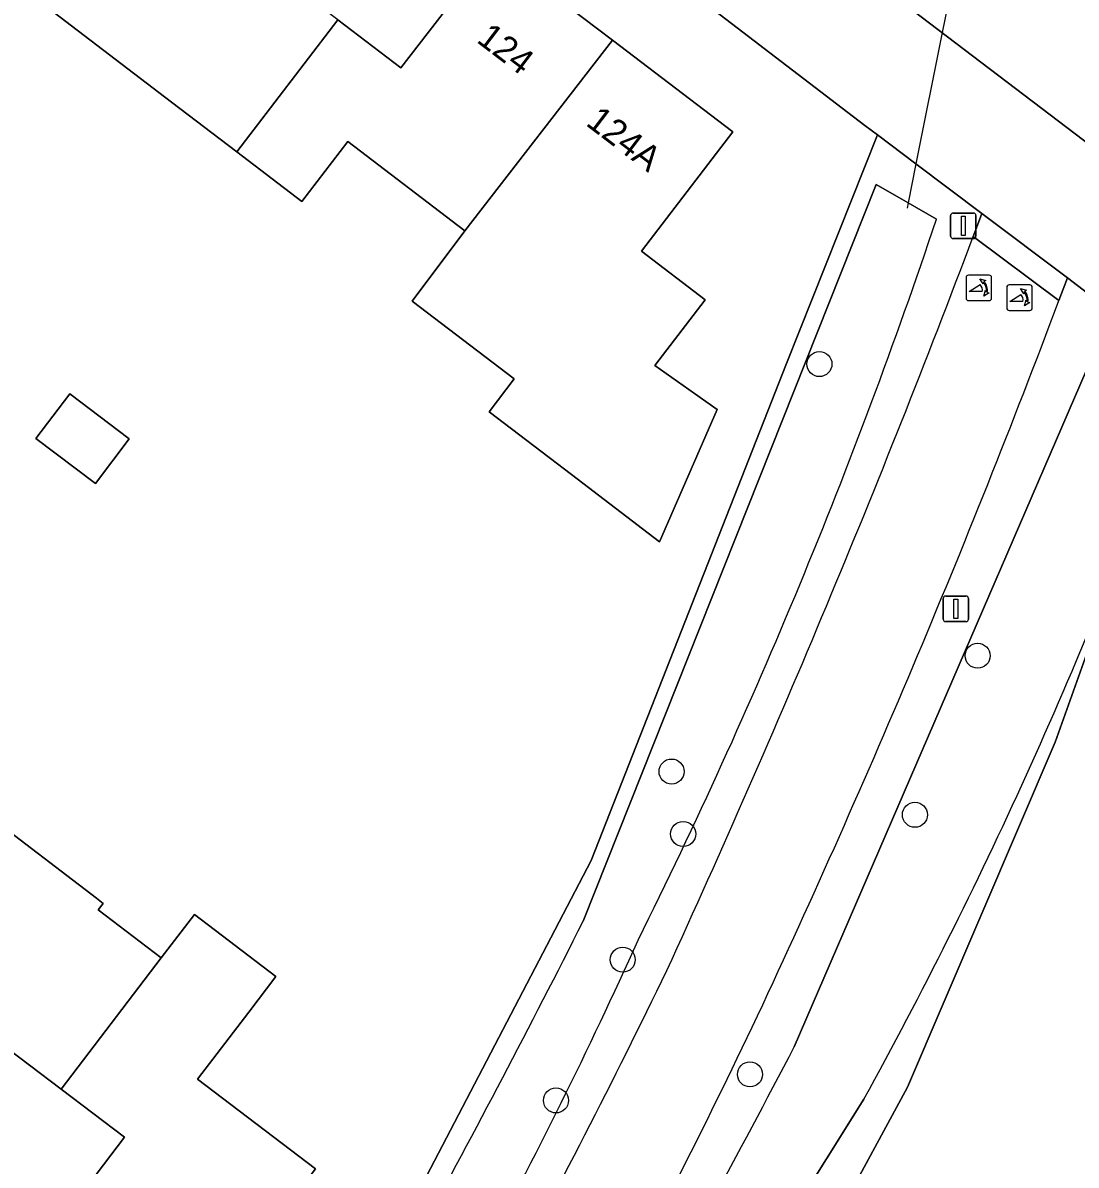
# Model space of a CAD drawing. Extents: x 159626 to 160723, y 388173 to 389416.
# Drawn here: x 160399.5 to 160440.65, y 388606.29 to 388650.92 of the extents above; entities that cross this region are included whole.
import ezdxf

# ---------------------------------------------------------------- set-up
doc = ezdxf.new("R2010")
doc.units = 0
for name, color, linetype in [('IMGEO_Berm_groen', 7, 'Continuous'), ('IMGEO_Boom', 7, 'Continuous'), ('IMGEO_Duiker', 7, 'Continuous'), ('IMGEO_Erf', 7, 'Continuous'), ('IMGEO_Fietspad_gesloten', 7, 'Continuous'), ('IMGEO_Lichtmast', 7, 'Continuous'), ('IMGEO_Pand', 7, 'Continuous'), ('IMGEO_Pand_nummerreeks', 7, 'Continuous'), ('IMGEO_Poller', 7, 'Continuous'), ('IMGEO_Rijbaan_lokaal_open', 7, 'Continuous'), ('IMGEO_Verkeersbordpaal', 7, 'Continuous'), ('IMGEO_Voetpad_open', 7, 'Continuous'), ('IMGEO_Waterloop', 7, 'Continuous')]:
    doc.layers.add(name, color=color, linetype=linetype)

msp = doc.modelspace()

# ---------------------------------------------------------------- linework, layer by layer
at = {"layer": 'IMGEO_Berm_groen'}
for points in [[(160436.965, 388643.472), (160434.385, 388645.415), (160432.882, 388646.546), (160429.331, 388637.607), (160421.697, 388618.19), (160411.017, 388597.713), (160407.654, 388591.157), (160410.924, 388588.72)], [(160421.39, 388615.827), (160432.829, 388644.603), (160434.08, 388643.886), (160435.187, 388643.251)], [(160436.628, 388642.576), (160436.797, 388643.024), (160436.965, 388643.472)], [(160429.634, 388610.908), (160441.529, 388638.466), (160442.538, 388637.837), (160444.706, 388636.484), (160445.015, 388637.348), (160442.866, 388638.996), (160440.306, 388640.958), (160440.14, 388640.514), (160439.973, 388640.071)], [(160426.76, 388595.873), (160434.06, 388609.33), (160439.82, 388622.82), (160444.055, 388634.663)], [(160432.356, 388608.864), (160417.502, 388585.138), (160416.544, 388585.792), (160415.731, 388586.347)]]:
    msp.add_lwpolyline(points, dxfattribs=at)
for centre, radius, start, end in [((160226.048, 388713.301), 220.559, 333.55502, 341.48192), ((160017.272, 388800.831), 448.223, 335.35161, 339.3247), ((160074.328, 388777.667), 390.678, 334.85848, 339.37824), ((160271.208, 388697.491), 183.911, 331.19029, 340.02424), ((160041.141, 388807.495), 425.823, 329.54554, 333.24916), ((160256.085, 388690.215), 183.529, 327.06662, 335.83276), ((160162.588, 388740.475), 291.034, 328.57145, 334.22007), ((160187.153, 388726.776), 266.927, 328.24692, 334.45817), ((160048.912, 388810.204), 429.73, 328.60572, 332.36935)]:
    msp.add_arc(centre, radius, start, end, dxfattribs=at)
at = {"layer": 'IMGEO_Boom'}
for centre in [(160430.617, 388637.59), (160436.797, 388626.194), (160424.838, 388621.669), (160434.346, 388619.978), (160425.293, 388619.229), (160422.931, 388614.317), (160427.902, 388609.836), (160420.323, 388608.816)]:
    msp.add_circle(centre, 0.489, dxfattribs=at)
at = {"layer": 'IMGEO_Duiker'}
msp.add_lwpolyline([(160439.097, 388669.047), (160438.998, 388668.552), (160437.72, 388662.006), (160437.338, 388659.826), (160436.892, 388657.762), (160435.422, 388650.617), (160434.385, 388645.415), (160434.08, 388643.886), (160434.039, 388643.681)], dxfattribs=at)
at = {"layer": 'IMGEO_Erf'}
for points in [[(160356.325, 388630.244), (160407.654, 388591.157), (160411.017, 388597.713), (160421.697, 388618.19), (160429.331, 388637.607), (160432.882, 388646.546), (160432.389, 388646.917), (160387.612, 388681.185)], [(160411.806, 388651.036), (160414.264, 388649.166), (160417.85, 388653.808), (160422.533, 388650.244), (160427.228, 388646.671), (160423.669, 388641.996), (160426.146, 388640.101), (160424.19, 388637.54), (160426.626, 388635.819), (160424.37, 388630.648), (160420.93, 388633.27), (160417.712, 388635.723), (160418.693, 388637.01), (160414.71, 388640.047), (160416.757, 388642.798), (160412.188, 388646.282), (160410.401, 388643.937), (160407.85, 388645.882), (160405.307, 388647.822), (160400.68, 388651.352)], [(160473.922, 388615.363), (160452.411, 388631.678), (160445.015, 388637.348), (160444.706, 388636.484), (160444.055, 388634.663), (160439.82, 388622.82), (160434.06, 388609.33), (160426.76, 388595.873), (160418.317, 388583.095), (160421.291, 388580.817), (160422.334, 388579.975)], [(160397.998, 388620.049), (160402.373, 388616.718), (160402.636, 388616.517), (160402.442, 388616.263), (160404.906, 388614.386), (160406.197, 388616.078), (160409.378, 388613.655), (160408.321, 388612.267), (160406.325, 388609.648), (160410.93, 388606.14), (160405.212, 388598.62), (160399.901, 388602.678), (160403.463, 388607.383), (160400.99, 388609.256), (160398.507, 388611.135)]]:
    msp.add_lwpolyline(points, dxfattribs=at)
msp.add_lwpolyline([(160403.654, 388634.669), (160402.335, 388632.923), (160400.008, 388634.681), (160401.328, 388636.427)], close=True, dxfattribs=at)
at = {"layer": 'IMGEO_Fietspad_gesloten'}
msp.add_lwpolyline([(160439.973, 388640.071), (160436.628, 388642.576)], dxfattribs=at)
for centre, radius, start, end in [((160017.272, 388800.831), 448.223, 335.35161, 339.3247), ((160074.328, 388777.667), 390.678, 334.85848, 339.37824), ((160162.588, 388740.475), 291.034, 328.57145, 334.22007), ((160187.153, 388726.776), 266.927, 328.24692, 334.45817)]:
    msp.add_arc(centre, radius, start, end, dxfattribs=at)
at = {"layer": 'IMGEO_Lichtmast'}
for p, q in [((160435.449, 388627.627), (160435.449, 388628.427)), ((160435.449, 388628.427), (160435.449, 388627.627)), ((160435.549, 388628.527), (160436.339, 388628.527)), ((160436.339, 388628.527), (160435.549, 388628.527)), ((160436.439, 388628.427), (160436.439, 388627.627)), ((160436.439, 388627.627), (160436.439, 388628.427)), ((160436.339, 388627.527), (160435.549, 388627.527)), ((160435.549, 388627.527), (160436.339, 388627.527))]:
    msp.add_line(p, q, dxfattribs=at)
msp.add_lwpolyline([(160435.869, 388628.402), (160436.019, 388628.402), (160436.019, 388627.652), (160435.869, 388627.652), (160435.869, 388628.402)], dxfattribs=at)
for centre, start, end in [((160435.549, 388628.427), 90, 180), ((160435.549, 388628.427), 90, 180), ((160436.339, 388628.427), 0, 90), ((160436.339, 388628.427), 360, 90), ((160435.549, 388627.627), 180, 270), ((160435.549, 388627.627), 180, 270), ((160436.339, 388627.627), 270, 0), ((160436.339, 388627.627), 270, 0)]:
    msp.add_arc(centre, 0.1, start, end, dxfattribs=at)
at = {"layer": 'IMGEO_Pand'}
for points in [[(160407.85, 388645.882), (160411.806, 388651.036), (160409.34, 388652.912), (160412.874, 388657.59), (160408.217, 388661.161), (160400.68, 388651.352), (160405.307, 388647.822)], [(160416.757, 388642.798), (160422.533, 388650.244), (160417.85, 388653.808), (160414.264, 388649.166), (160411.806, 388651.036), (160407.85, 388645.882), (160410.401, 388643.937), (160412.188, 388646.282)], [(160423.669, 388641.996), (160427.228, 388646.671), (160422.533, 388650.244), (160416.757, 388642.798), (160414.71, 388640.047), (160418.693, 388637.01), (160417.712, 388635.723), (160420.93, 388633.27), (160424.37, 388630.648), (160426.626, 388635.819), (160424.19, 388637.54), (160426.146, 388640.101)], [(160403.654, 388634.669), (160401.328, 388636.427), (160400.008, 388634.681), (160402.335, 388632.923)], [(160404.906, 388614.386), (160402.442, 388616.263), (160402.636, 388616.517), (160402.373, 388616.718), (160397.998, 388620.049), (160390.272, 388610.022), (160394.951, 388606.438), (160398.507, 388611.135), (160400.99, 388609.256)], [(160404.906, 388614.386), (160400.99, 388609.256), (160403.463, 388607.383), (160399.901, 388602.678), (160405.212, 388598.62), (160410.93, 388606.14), (160406.325, 388609.648), (160408.321, 388612.267), (160409.378, 388613.655), (160406.197, 388616.078)]]:
    msp.add_lwpolyline(points, close=True, dxfattribs=at)
at = {"layer": 'IMGEO_Poller'}
for p, q in [((160436.343, 388640.97), (160436.343, 388640.163)), ((160436.343, 388640.97), (160436.343, 388640.163)), ((160437.245, 388641.065), (160436.437, 388641.065)), ((160437.245, 388641.065), (160436.437, 388641.065)), ((160437.339, 388640.163), (160437.339, 388640.97)), ((160437.339, 388640.163), (160437.339, 388640.97)), ((160438.835, 388640.683), (160438.027, 388640.683)), ((160438.835, 388640.683), (160438.027, 388640.683)), ((160437.933, 388640.588), (160437.933, 388639.781)), ((160437.933, 388640.588), (160437.933, 388639.781)), ((160438.929, 388639.781), (160438.929, 388640.588)), ((160438.929, 388639.781), (160438.929, 388640.588)), ((160436.437, 388640.068), (160437.245, 388640.068)), ((160436.437, 388640.068), (160437.245, 388640.068)), ((160438.027, 388639.686), (160438.835, 388639.686)), ((160438.027, 388639.686), (160438.835, 388639.686))]:
    msp.add_line(p, q, dxfattribs=at)
for points in [[(160436.978, 388640.421), (160436.465, 388640.421), (160436.895, 388640.696)], [(160437.022, 388640.794), (160437.01, 388640.721), (160436.885, 388640.926)], [(160436.885, 388640.926), (160437.116, 388640.86), (160437.045, 388640.828)], [(160437.038, 388640.249), (160437.104, 388640.48), (160437.134, 388640.412)], [(160437.17, 388640.385), (160437.242, 388640.374), (160437.038, 388640.249)], [(160438.568, 388640.039), (160438.055, 388640.039), (160438.485, 388640.314)], [(160438.612, 388640.412), (160438.6, 388640.339), (160438.475, 388640.544)], [(160438.475, 388640.544), (160438.706, 388640.478), (160438.635, 388640.446)], [(160438.628, 388639.867), (160438.694, 388640.098), (160438.724, 388640.03)], [(160438.76, 388640.003), (160438.832, 388639.992), (160438.628, 388639.867)]]:
    msp.add_lwpolyline(points, dxfattribs=at)
for centre, radius, start, end in [((160436.437, 388640.97), 0.0946, 90, 180), ((160436.437, 388640.97), 0.0946, 90, 180), ((160436.65, 388640.471), 0.332, 351.3247, 42.4854), ((160436.664, 388640.481), 0.476, 351.7527, 41.1691), ((160436.664, 388640.481), 0.516, 349.3569, 42.2912), ((160437.245, 388640.97), 0.0946, 0, 90), ((160437.245, 388640.97), 0.0946, 0, 90), ((160438.027, 388640.588), 0.0946, 90, 180), ((160438.027, 388640.588), 0.0946, 90, 180), ((160438.835, 388640.588), 0.0946, 0, 90), ((160438.835, 388640.588), 0.0946, 0, 90), ((160438.24, 388640.089), 0.332, 351.3247, 42.4854), ((160438.254, 388640.099), 0.476, 351.7527, 41.1691), ((160438.254, 388640.099), 0.516, 349.3569, 42.2912), ((160436.437, 388640.163), 0.0946, 180, 270), ((160436.437, 388640.163), 0.0946, 180, 270), ((160437.245, 388640.163), 0.0946, 270, 0), ((160437.245, 388640.163), 0.0946, 270, 0), ((160438.027, 388639.781), 0.0946, 180, 270), ((160438.027, 388639.781), 0.0946, 180, 270), ((160438.835, 388639.781), 0.0946, 270, 0), ((160438.835, 388639.781), 0.0946, 270, 0)]:
    msp.add_arc(centre, radius, start, end, dxfattribs=at)
at = {"layer": 'IMGEO_Rijbaan_lokaal_open'}
msp.add_lwpolyline([(160435.247, 388658.875), (160434.926, 388659.154), (160430.911, 388653.976), (160445.327, 388643.009), (160449.379, 388648.196), (160446.896, 388650.101)], dxfattribs=at)
msp.add_lwpolyline([(160436.628, 388642.576), (160439.973, 388640.071), (160440.14, 388640.514), (160440.306, 388640.958), (160436.965, 388643.472), (160436.797, 388643.024)], close=True, dxfattribs=at)
at = {"layer": 'IMGEO_Verkeersbordpaal'}
for p, q in [((160435.74, 388642.593), (160435.74, 388643.393)), ((160435.74, 388643.393), (160435.74, 388642.593)), ((160435.84, 388643.493), (160436.63, 388643.493)), ((160436.63, 388643.493), (160435.84, 388643.493)), ((160436.73, 388643.393), (160436.73, 388642.593)), ((160436.73, 388642.593), (160436.73, 388643.393)), ((160436.63, 388642.493), (160435.84, 388642.493)), ((160435.84, 388642.493), (160436.63, 388642.493))]:
    msp.add_line(p, q, dxfattribs=at)
msp.add_lwpolyline([(160436.16, 388643.368), (160436.31, 388643.368), (160436.31, 388642.618), (160436.16, 388642.618), (160436.16, 388643.368)], dxfattribs=at)
for centre, start, end in [((160435.84, 388643.393), 90, 180), ((160435.84, 388643.393), 90, 180), ((160436.63, 388643.393), 0, 90), ((160436.63, 388643.393), 360, 90), ((160435.84, 388642.593), 180, 270), ((160435.84, 388642.593), 180, 270), ((160436.63, 388642.593), 270, 0), ((160436.63, 388642.593), 270, 0)]:
    msp.add_arc(centre, 0.1, start, end, dxfattribs=at)
at = {"layer": 'IMGEO_Voetpad_open'}
msp.add_lwpolyline([(160387.612, 388681.185), (160432.389, 388646.917), (160432.882, 388646.546), (160434.385, 388645.415), (160436.965, 388643.472), (160440.306, 388640.958), (160442.866, 388638.996), (160445.015, 388637.348), (160447.964, 388641.112), (160447.348, 388641.481), (160445.327, 388643.009), (160430.911, 388653.976), (160428.883, 388655.496)], dxfattribs=at)
at = {"layer": 'IMGEO_Waterloop'}
for points in [[(160435.187, 388643.251), (160434.08, 388643.886), (160432.829, 388644.603), (160421.39, 388615.827)], [(160444.055, 388634.663), (160444.706, 388636.484), (160442.538, 388637.837), (160441.529, 388638.466), (160429.634, 388610.908)], [(160415.731, 388586.347), (160416.544, 388585.792), (160417.502, 388585.138), (160432.356, 388608.864)]]:
    msp.add_lwpolyline(points, dxfattribs=at)
for centre, radius, start, end in [((160226.048, 388713.301), 220.559, 333.55502, 341.48192), ((160271.208, 388697.491), 183.911, 331.19029, 340.02424), ((160041.141, 388807.495), 425.823, 329.54554, 333.24916), ((160256.085, 388690.215), 183.529, 327.06662, 335.83276), ((160048.912, 388810.204), 429.73, 328.60572, 332.36935)]:
    msp.add_arc(centre, radius, start, end, dxfattribs=at)

# ---------------------------------------------------------------- texts
at = {"layer": 'IMGEO_Pand_nummerreeks'}
for s, p in [('124', (160417.181, 388650.195)), ('124A', (160421.448, 388646.948))]:
    msp.add_text(s, height=1, rotation=322.7275, dxfattribs=at).set_placement(p)

doc.saveas('drawing.dxf')
